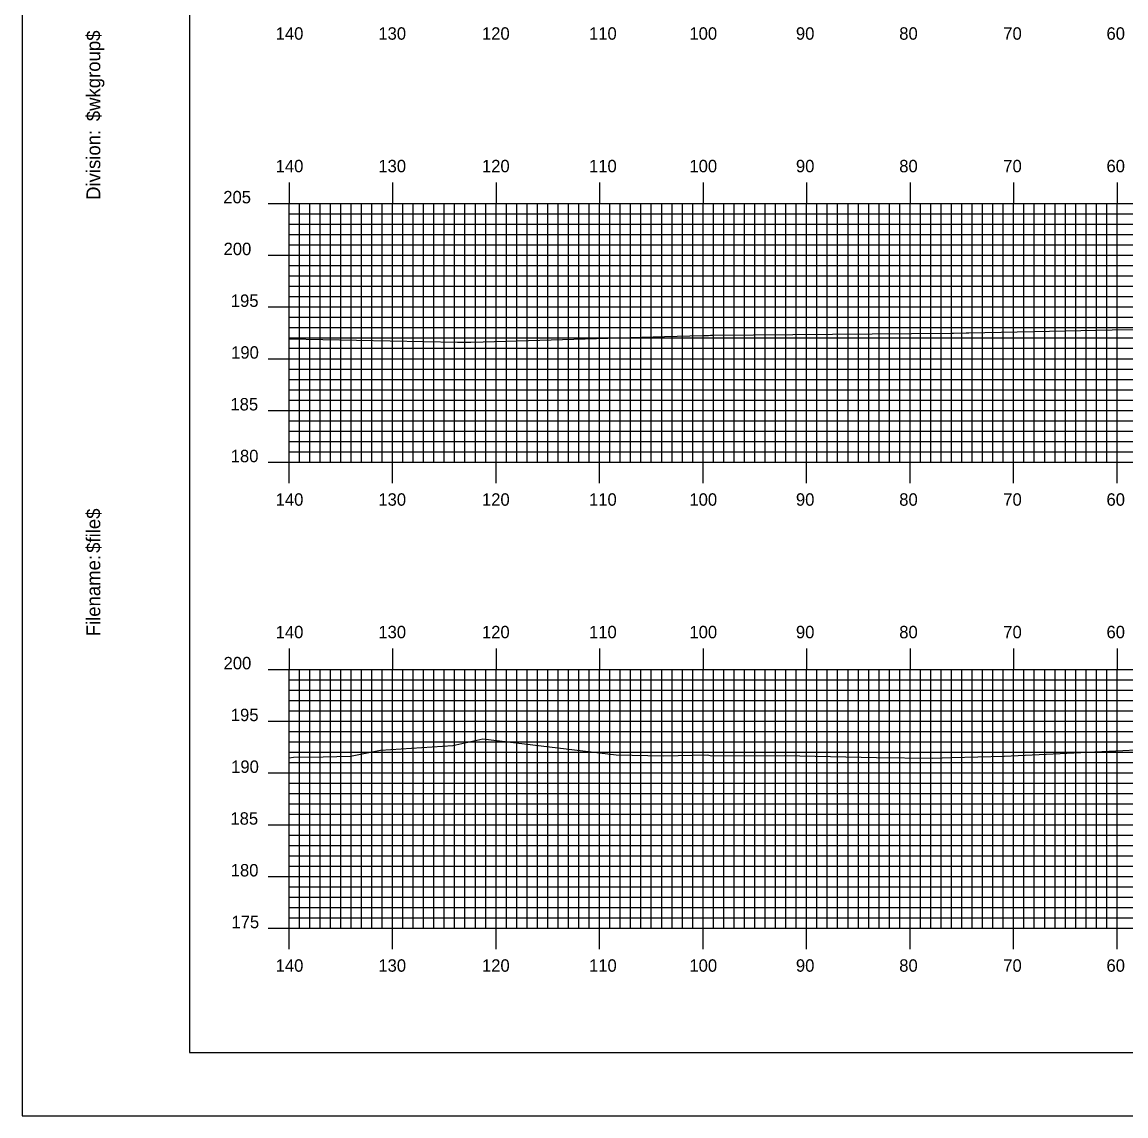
# Model space of a CAD drawing. Extents: x 1798388 to 1798731, y 442591 to 442811.
# Drawn here: x 1798387.7 to 1798494.3, y 442590.5 to 442696.2 of the extents above; entities that cross this region are included whole.
import ezdxf

# ---------------------------------------------------------------- set-up
doc = ezdxf.new("R2010")
doc.units = 0
for name, color, linetype in [('BORDER', 7, 'Continuous'), ('H_V ANNOTATION', 7, 'Continuous'), ('MAJOR', 7, 'Continuous'), ('MINOR', 7, 'Continuous'), ('PLOT BOUNDARY', 7, 'Continuous'), ('S_Roadway_Centerline', 7, 'Continuous')]:
    doc.layers.add(name, color=color, linetype=linetype)

msp = doc.modelspace()

# ---------------------------------------------------------------- linework, layer by layer
at = {"layer": 'BORDER'}
msp.add_lwpolyline([(1798403.87, 442596.67), (1798723.87, 442596.67), (1798723.87, 442806.67), (1798403.87, 442806.67)], close=True, dxfattribs=at)
at = {"layer": 'MAJOR'}
for p, q in [((1798413.47, 442680.67), (1798413.47, 442678.67)), ((1798423.47, 442680.67), (1798423.47, 442678.67)), ((1798433.47, 442680.67), (1798433.47, 442678.67)), ((1798443.47, 442680.67), (1798443.47, 442678.67)), ((1798453.47, 442680.67), (1798453.47, 442678.67)), ((1798463.47, 442680.67), (1798463.47, 442678.67)), ((1798473.47, 442680.67), (1798473.47, 442678.67)), ((1798483.47, 442680.67), (1798483.47, 442678.67)), ((1798493.47, 442680.67), (1798493.47, 442678.67)), ((1798411.47, 442678.67), (1798413.47, 442678.67)), ((1798413.47, 442678.67), (1798693.47, 442678.67)), ((1798413.47, 442653.67), (1798413.47, 442678.67)), ((1798413.47, 442653.67), (1798413.47, 442678.67)), ((1798413.47, 442678.67), (1798693.47, 442678.67)), ((1798423.47, 442653.67), (1798423.47, 442678.67)), ((1798433.47, 442653.67), (1798433.47, 442678.67)), ((1798443.47, 442653.67), (1798443.47, 442678.67)), ((1798453.47, 442653.67), (1798453.47, 442678.67)), ((1798463.47, 442653.67), (1798463.47, 442678.67)), ((1798473.47, 442653.67), (1798473.47, 442678.67)), ((1798483.47, 442653.67), (1798483.47, 442678.67)), ((1798493.47, 442653.67), (1798493.47, 442678.67)), ((1798411.47, 442673.67), (1798413.47, 442673.67)), ((1798413.47, 442673.67), (1798693.47, 442673.67)), ((1798411.47, 442668.67), (1798413.47, 442668.67)), ((1798413.47, 442668.67), (1798693.47, 442668.67)), ((1798411.47, 442663.67), (1798413.47, 442663.67)), ((1798413.47, 442663.67), (1798693.47, 442663.67)), ((1798411.47, 442658.67), (1798413.47, 442658.67)), ((1798413.47, 442658.67), (1798693.47, 442658.67)), ((1798411.47, 442653.67), (1798413.47, 442653.67)), ((1798413.47, 442653.67), (1798693.47, 442653.67)), ((1798413.47, 442653.67), (1798693.47, 442653.67)), ((1798413.47, 442651.66), (1798413.47, 442653.67)), ((1798423.47, 442651.66), (1798423.47, 442653.67)), ((1798433.47, 442651.66), (1798433.47, 442653.67)), ((1798443.47, 442651.66), (1798443.47, 442653.67)), ((1798453.47, 442651.66), (1798453.47, 442653.67)), ((1798463.47, 442651.66), (1798463.47, 442653.67)), ((1798473.47, 442651.66), (1798473.47, 442653.67)), ((1798483.47, 442651.66), (1798483.47, 442653.67)), ((1798493.47, 442651.66), (1798493.47, 442653.67)), ((1798413.47, 442635.67), (1798413.47, 442633.67)), ((1798423.47, 442635.67), (1798423.47, 442633.67)), ((1798433.47, 442635.67), (1798433.47, 442633.67)), ((1798443.47, 442635.67), (1798443.47, 442633.67)), ((1798453.47, 442635.67), (1798453.47, 442633.67)), ((1798463.47, 442635.67), (1798463.47, 442633.67)), ((1798473.47, 442635.67), (1798473.47, 442633.67)), ((1798483.47, 442635.67), (1798483.47, 442633.67)), ((1798493.47, 442635.67), (1798493.47, 442633.67)), ((1798411.47, 442633.67), (1798413.47, 442633.67)), ((1798413.47, 442633.67), (1798693.47, 442633.67)), ((1798413.47, 442608.67), (1798413.47, 442633.67)), ((1798413.47, 442608.67), (1798413.47, 442633.67)), ((1798413.47, 442633.67), (1798693.47, 442633.67)), ((1798423.47, 442608.67), (1798423.47, 442633.67)), ((1798433.47, 442608.67), (1798433.47, 442633.67)), ((1798443.47, 442608.67), (1798443.47, 442633.67)), ((1798453.47, 442608.67), (1798453.47, 442633.67)), ((1798463.47, 442608.67), (1798463.47, 442633.67)), ((1798473.47, 442608.67), (1798473.47, 442633.67)), ((1798483.47, 442608.67), (1798483.47, 442633.67)), ((1798493.47, 442608.67), (1798493.47, 442633.67)), ((1798411.47, 442628.67), (1798413.47, 442628.67)), ((1798413.47, 442628.67), (1798693.47, 442628.67)), ((1798411.47, 442623.67), (1798413.47, 442623.67)), ((1798413.47, 442623.67), (1798693.47, 442623.67)), ((1798411.47, 442618.67), (1798413.47, 442618.67)), ((1798413.47, 442618.67), (1798693.47, 442618.67)), ((1798411.47, 442613.67), (1798413.47, 442613.67)), ((1798413.47, 442613.67), (1798693.47, 442613.67)), ((1798411.47, 442608.67), (1798413.47, 442608.67)), ((1798413.47, 442608.67), (1798693.47, 442608.67)), ((1798413.47, 442608.67), (1798693.47, 442608.67)), ((1798413.47, 442606.66), (1798413.47, 442608.67)), ((1798423.47, 442606.66), (1798423.47, 442608.67)), ((1798433.47, 442606.66), (1798433.47, 442608.67)), ((1798443.47, 442606.66), (1798443.47, 442608.67)), ((1798453.47, 442606.66), (1798453.47, 442608.67)), ((1798463.47, 442606.66), (1798463.47, 442608.67)), ((1798473.47, 442606.66), (1798473.47, 442608.67)), ((1798483.47, 442606.66), (1798483.47, 442608.67)), ((1798493.47, 442606.66), (1798493.47, 442608.67))]:
    msp.add_line(p, q, dxfattribs=at)
at = {"layer": 'MINOR'}
for p, q in [((1798414.47, 442653.67), (1798414.47, 442678.67)), ((1798415.47, 442653.67), (1798415.47, 442678.67)), ((1798416.47, 442653.67), (1798416.47, 442678.67)), ((1798417.47, 442653.67), (1798417.47, 442678.67)), ((1798418.47, 442653.67), (1798418.47, 442678.67)), ((1798419.47, 442653.67), (1798419.47, 442678.67)), ((1798420.47, 442653.67), (1798420.47, 442678.67)), ((1798421.47, 442653.67), (1798421.47, 442678.67)), ((1798422.47, 442653.67), (1798422.47, 442678.67)), ((1798424.47, 442653.67), (1798424.47, 442678.67)), ((1798425.47, 442653.67), (1798425.47, 442678.67)), ((1798426.47, 442653.67), (1798426.47, 442678.67)), ((1798427.47, 442653.67), (1798427.47, 442678.67)), ((1798428.47, 442653.67), (1798428.47, 442678.67)), ((1798429.47, 442653.67), (1798429.47, 442678.67)), ((1798430.47, 442653.67), (1798430.47, 442678.67)), ((1798431.47, 442653.67), (1798431.47, 442678.67)), ((1798432.47, 442653.67), (1798432.47, 442678.67)), ((1798434.47, 442653.67), (1798434.47, 442678.67)), ((1798435.47, 442653.67), (1798435.47, 442678.67)), ((1798436.47, 442653.67), (1798436.47, 442678.67)), ((1798437.47, 442653.67), (1798437.47, 442678.67)), ((1798438.47, 442653.67), (1798438.47, 442678.67)), ((1798439.47, 442653.67), (1798439.47, 442678.67)), ((1798440.47, 442653.67), (1798440.47, 442678.67)), ((1798441.47, 442653.67), (1798441.47, 442678.67)), ((1798442.47, 442653.67), (1798442.47, 442678.67)), ((1798444.47, 442653.67), (1798444.47, 442678.67)), ((1798445.47, 442653.67), (1798445.47, 442678.67)), ((1798446.47, 442653.67), (1798446.47, 442678.67)), ((1798447.47, 442653.67), (1798447.47, 442678.67)), ((1798448.47, 442653.67), (1798448.47, 442678.67)), ((1798449.47, 442653.67), (1798449.47, 442678.67)), ((1798450.47, 442653.67), (1798450.47, 442678.67)), ((1798451.47, 442653.67), (1798451.47, 442678.67)), ((1798452.47, 442653.67), (1798452.47, 442678.67)), ((1798454.47, 442653.67), (1798454.47, 442678.67)), ((1798455.47, 442653.67), (1798455.47, 442678.67)), ((1798456.47, 442653.67), (1798456.47, 442678.67)), ((1798457.47, 442653.67), (1798457.47, 442678.67)), ((1798458.47, 442653.67), (1798458.47, 442678.67)), ((1798459.47, 442653.67), (1798459.47, 442678.67)), ((1798460.47, 442653.67), (1798460.47, 442678.67)), ((1798461.47, 442653.67), (1798461.47, 442678.67)), ((1798462.47, 442653.67), (1798462.47, 442678.67)), ((1798464.47, 442653.67), (1798464.47, 442678.67)), ((1798465.47, 442653.67), (1798465.47, 442678.67)), ((1798466.47, 442653.67), (1798466.47, 442678.67)), ((1798467.47, 442653.67), (1798467.47, 442678.67)), ((1798468.47, 442653.67), (1798468.47, 442678.67)), ((1798469.47, 442653.67), (1798469.47, 442678.67)), ((1798470.47, 442653.67), (1798470.47, 442678.67)), ((1798471.47, 442653.67), (1798471.47, 442678.67)), ((1798472.47, 442653.67), (1798472.47, 442678.67)), ((1798474.47, 442653.67), (1798474.47, 442678.67)), ((1798475.47, 442653.67), (1798475.47, 442678.67)), ((1798476.47, 442653.67), (1798476.47, 442678.67)), ((1798477.47, 442653.67), (1798477.47, 442678.67)), ((1798478.47, 442653.67), (1798478.47, 442678.67)), ((1798479.47, 442653.67), (1798479.47, 442678.67)), ((1798480.47, 442653.67), (1798480.47, 442678.67)), ((1798481.47, 442653.67), (1798481.47, 442678.67)), ((1798482.47, 442653.67), (1798482.47, 442678.67)), ((1798484.47, 442653.67), (1798484.47, 442678.67)), ((1798485.47, 442653.67), (1798485.47, 442678.67)), ((1798486.47, 442653.67), (1798486.47, 442678.67)), ((1798487.47, 442653.67), (1798487.47, 442678.67)), ((1798488.47, 442653.67), (1798488.47, 442678.67)), ((1798489.47, 442653.67), (1798489.47, 442678.67)), ((1798490.47, 442653.67), (1798490.47, 442678.67)), ((1798491.47, 442653.67), (1798491.47, 442678.67)), ((1798492.47, 442653.67), (1798492.47, 442678.67)), ((1798413.47, 442677.67), (1798693.47, 442677.67)), ((1798413.47, 442677.67), (1798415.47, 442677.67)), ((1798413.47, 442676.67), (1798693.47, 442676.67)), ((1798413.47, 442676.67), (1798415.47, 442676.67)), ((1798413.47, 442675.67), (1798693.47, 442675.67)), ((1798413.47, 442675.67), (1798415.47, 442675.67)), ((1798413.47, 442674.67), (1798693.47, 442674.67)), ((1798413.47, 442674.67), (1798415.47, 442674.67)), ((1798413.47, 442672.67), (1798693.47, 442672.67)), ((1798413.47, 442672.67), (1798415.47, 442672.67)), ((1798413.47, 442671.67), (1798693.47, 442671.67)), ((1798413.47, 442671.67), (1798415.47, 442671.67)), ((1798413.47, 442670.67), (1798693.47, 442670.67)), ((1798413.47, 442670.67), (1798415.47, 442670.67)), ((1798413.47, 442669.67), (1798693.47, 442669.67)), ((1798413.47, 442669.67), (1798415.47, 442669.67)), ((1798413.47, 442667.67), (1798693.47, 442667.67)), ((1798413.47, 442667.67), (1798415.47, 442667.67)), ((1798413.47, 442666.67), (1798693.47, 442666.67)), ((1798413.47, 442666.67), (1798415.47, 442666.67)), ((1798413.47, 442665.67), (1798693.47, 442665.67)), ((1798413.47, 442665.67), (1798415.47, 442665.67)), ((1798413.47, 442664.67), (1798693.47, 442664.67)), ((1798413.47, 442664.67), (1798415.47, 442664.67)), ((1798413.47, 442662.67), (1798693.47, 442662.67)), ((1798413.47, 442662.67), (1798415.47, 442662.67)), ((1798413.47, 442661.67), (1798693.47, 442661.67)), ((1798413.47, 442661.67), (1798415.47, 442661.67)), ((1798413.47, 442660.67), (1798693.47, 442660.67)), ((1798413.47, 442660.67), (1798415.47, 442660.67)), ((1798413.47, 442659.67), (1798693.47, 442659.67)), ((1798413.47, 442659.67), (1798415.47, 442659.67)), ((1798413.47, 442657.67), (1798693.47, 442657.67)), ((1798413.47, 442657.67), (1798415.47, 442657.67)), ((1798413.47, 442656.67), (1798693.47, 442656.67)), ((1798413.47, 442656.67), (1798415.47, 442656.67)), ((1798413.47, 442655.67), (1798693.47, 442655.67)), ((1798413.47, 442655.67), (1798415.47, 442655.67)), ((1798413.47, 442654.67), (1798693.47, 442654.67)), ((1798413.47, 442654.67), (1798415.47, 442654.67)), ((1798414.47, 442608.67), (1798414.47, 442633.67)), ((1798415.47, 442608.67), (1798415.47, 442633.67)), ((1798416.47, 442608.67), (1798416.47, 442633.67)), ((1798417.47, 442608.67), (1798417.47, 442633.67)), ((1798418.47, 442608.67), (1798418.47, 442633.67)), ((1798419.47, 442608.67), (1798419.47, 442633.67)), ((1798420.47, 442608.67), (1798420.47, 442633.67)), ((1798421.47, 442608.67), (1798421.47, 442633.67)), ((1798422.47, 442608.67), (1798422.47, 442633.67)), ((1798424.47, 442608.67), (1798424.47, 442633.67)), ((1798425.47, 442608.67), (1798425.47, 442633.67)), ((1798426.47, 442608.67), (1798426.47, 442633.67)), ((1798427.47, 442608.67), (1798427.47, 442633.67)), ((1798428.47, 442608.67), (1798428.47, 442633.67)), ((1798429.47, 442608.67), (1798429.47, 442633.67)), ((1798430.47, 442608.67), (1798430.47, 442633.67)), ((1798431.47, 442608.67), (1798431.47, 442633.67)), ((1798432.47, 442608.67), (1798432.47, 442633.67)), ((1798434.47, 442608.67), (1798434.47, 442633.67)), ((1798435.47, 442608.67), (1798435.47, 442633.67)), ((1798436.47, 442608.67), (1798436.47, 442633.67)), ((1798437.47, 442608.67), (1798437.47, 442633.67)), ((1798438.47, 442608.67), (1798438.47, 442633.67)), ((1798439.47, 442608.67), (1798439.47, 442633.67)), ((1798440.47, 442608.67), (1798440.47, 442633.67)), ((1798441.47, 442608.67), (1798441.47, 442633.67)), ((1798442.47, 442608.67), (1798442.47, 442633.67)), ((1798444.47, 442608.67), (1798444.47, 442633.67)), ((1798445.47, 442608.67), (1798445.47, 442633.67)), ((1798446.47, 442608.67), (1798446.47, 442633.67)), ((1798447.47, 442608.67), (1798447.47, 442633.67)), ((1798448.47, 442608.67), (1798448.47, 442633.67)), ((1798449.47, 442608.67), (1798449.47, 442633.67)), ((1798450.47, 442608.67), (1798450.47, 442633.67)), ((1798451.47, 442608.67), (1798451.47, 442633.67)), ((1798452.47, 442608.67), (1798452.47, 442633.67)), ((1798454.47, 442608.67), (1798454.47, 442633.67)), ((1798455.47, 442608.67), (1798455.47, 442633.67)), ((1798456.47, 442608.67), (1798456.47, 442633.67)), ((1798457.47, 442608.67), (1798457.47, 442633.67)), ((1798458.47, 442608.67), (1798458.47, 442633.67)), ((1798459.47, 442608.67), (1798459.47, 442633.67)), ((1798460.47, 442608.67), (1798460.47, 442633.67)), ((1798461.47, 442608.67), (1798461.47, 442633.67)), ((1798462.47, 442608.67), (1798462.47, 442633.67)), ((1798464.47, 442608.67), (1798464.47, 442633.67)), ((1798465.47, 442608.67), (1798465.47, 442633.67)), ((1798466.47, 442608.67), (1798466.47, 442633.67)), ((1798467.47, 442608.67), (1798467.47, 442633.67)), ((1798468.47, 442608.67), (1798468.47, 442633.67)), ((1798469.47, 442608.67), (1798469.47, 442633.67)), ((1798470.47, 442608.67), (1798470.47, 442633.67)), ((1798471.47, 442608.67), (1798471.47, 442633.67)), ((1798472.47, 442608.67), (1798472.47, 442633.67)), ((1798474.47, 442608.67), (1798474.47, 442633.67)), ((1798475.47, 442608.67), (1798475.47, 442633.67)), ((1798476.47, 442608.67), (1798476.47, 442633.67)), ((1798477.47, 442608.67), (1798477.47, 442633.67)), ((1798478.47, 442608.67), (1798478.47, 442633.67)), ((1798479.47, 442608.67), (1798479.47, 442633.67)), ((1798480.47, 442608.67), (1798480.47, 442633.67)), ((1798481.47, 442608.67), (1798481.47, 442633.67)), ((1798482.47, 442608.67), (1798482.47, 442633.67)), ((1798484.47, 442608.67), (1798484.47, 442633.67)), ((1798485.47, 442608.67), (1798485.47, 442633.67)), ((1798486.47, 442608.67), (1798486.47, 442633.67)), ((1798487.47, 442608.67), (1798487.47, 442633.67)), ((1798488.47, 442608.67), (1798488.47, 442633.67)), ((1798489.47, 442608.67), (1798489.47, 442633.67)), ((1798490.47, 442608.67), (1798490.47, 442633.67)), ((1798491.47, 442608.67), (1798491.47, 442633.67)), ((1798492.47, 442608.67), (1798492.47, 442633.67)), ((1798413.47, 442632.67), (1798693.47, 442632.67)), ((1798413.47, 442632.67), (1798415.47, 442632.67)), ((1798413.47, 442631.67), (1798693.47, 442631.67)), ((1798413.47, 442631.67), (1798415.47, 442631.67)), ((1798413.47, 442630.67), (1798693.47, 442630.67)), ((1798413.47, 442630.67), (1798415.47, 442630.67)), ((1798413.47, 442629.67), (1798693.47, 442629.67)), ((1798413.47, 442629.67), (1798415.47, 442629.67)), ((1798413.47, 442627.67), (1798693.47, 442627.67)), ((1798413.47, 442627.67), (1798415.47, 442627.67)), ((1798413.47, 442626.67), (1798693.47, 442626.67)), ((1798413.47, 442626.67), (1798415.47, 442626.67)), ((1798413.47, 442625.67), (1798693.47, 442625.67)), ((1798413.47, 442625.67), (1798415.47, 442625.67)), ((1798413.47, 442624.67), (1798693.47, 442624.67)), ((1798413.47, 442624.67), (1798415.47, 442624.67)), ((1798413.47, 442622.67), (1798693.47, 442622.67)), ((1798413.47, 442622.67), (1798415.47, 442622.67)), ((1798413.47, 442621.67), (1798693.47, 442621.67)), ((1798413.47, 442621.67), (1798415.47, 442621.67)), ((1798413.47, 442620.67), (1798693.47, 442620.67)), ((1798413.47, 442620.67), (1798415.47, 442620.67)), ((1798413.47, 442619.67), (1798693.47, 442619.67)), ((1798413.47, 442619.67), (1798415.47, 442619.67)), ((1798413.47, 442617.67), (1798693.47, 442617.67)), ((1798413.47, 442617.67), (1798415.47, 442617.67)), ((1798413.47, 442616.67), (1798693.47, 442616.67)), ((1798413.47, 442616.67), (1798415.47, 442616.67)), ((1798413.47, 442615.67), (1798693.47, 442615.67)), ((1798413.47, 442615.67), (1798415.47, 442615.67)), ((1798413.47, 442614.67), (1798693.47, 442614.67)), ((1798413.47, 442614.67), (1798415.47, 442614.67)), ((1798413.47, 442612.67), (1798693.47, 442612.67)), ((1798413.47, 442612.67), (1798415.47, 442612.67)), ((1798413.47, 442611.67), (1798693.47, 442611.67)), ((1798413.47, 442611.67), (1798415.47, 442611.67)), ((1798413.47, 442610.67), (1798693.47, 442610.67)), ((1798413.47, 442610.67), (1798415.47, 442610.67)), ((1798413.47, 442609.67), (1798693.47, 442609.67)), ((1798413.47, 442609.67), (1798415.47, 442609.67))]:
    msp.add_line(p, q, dxfattribs=at)
at = {"layer": 'PLOT BOUNDARY'}
msp.add_lwpolyline([(1798387.68, 442590.55), (1798727.68, 442590.55), (1798727.68, 442810.55), (1798387.68, 442810.55)], close=True, dxfattribs=at)
at = {"layer": 'S_Roadway_Centerline'}
for points in [[(1798413.47, 442665.57), (1798429.76, 442665.26), (1798431.05, 442665.27), (1798432.23, 442665.29), (1798449.74, 442665.81), (1798453.4, 442665.92), (1798453.62, 442665.92), (1798453.82, 442665.92), (1798453.89, 442665.92), (1798453.99, 442665.92), (1798454.19, 442665.93), (1798454.5, 442665.93), (1798477.45, 442666.13), (1798477.67, 442666.13), (1798478.9, 442666.15), (1798479.15, 442666.16), (1798486.95, 442666.32), (1798492.98, 442666.44), (1798497.86, 442666.51)], [(1798413.47, 442625.14), (1798413.91, 442625.2), (1798416.78, 442625.22), (1798419.4, 442625.28), (1798422.3, 442625.86), (1798429.3, 442626.32), (1798432.2, 442626.96), (1798445.09, 442625.41), (1798449.68, 442625.32), (1798453.88, 442625.42), (1798454.32, 442625.32), (1798461.34, 442625.35), (1798470.21, 442625.17), (1798475.66, 442625.09), (1798477.46, 442625.16), (1798482.57, 442625.27), (1798494.03, 442625.84), (1798495.29, 442625.9)]]:
    msp.add_lwpolyline(points, dxfattribs=at)

# ---------------------------------------------------------------- texts
at = {"layer": 'BORDER'}
for s, p in [('$wkgroup$', (1798395.24, 442686.6)), ('Division:', (1798395.24, 442679)), ('$file$', (1798395.24, 442644.92)), ('Filename:', (1798395.24, 442636.86))]:
    msp.add_text(s, height=1.339, rotation=90, dxfattribs=at).set_placement(p)
at = {"layer": 'H_V ANNOTATION'}
for s, p in [('140', (1798412.18, 442694.47)), ('130', (1798422.1, 442694.47)), ('120', (1798432.11, 442694.47)), ('110', (1798442.45, 442694.47)), ('100', (1798452.15, 442694.47)), ('90', (1798462.44, 442694.47)), ('80', (1798472.42, 442694.47)), ('70', (1798482.47, 442694.47)), ('60', (1798492.44, 442694.47)), ('140', (1798412.18, 442681.67)), ('130', (1798422.1, 442681.67)), ('120', (1798432.11, 442681.67)), ('110', (1798442.45, 442681.67)), ('100', (1798452.15, 442681.67)), ('90', (1798462.44, 442681.67)), ('80', (1798472.42, 442681.67)), ('70', (1798482.47, 442681.67)), ('60', (1798492.44, 442681.67)), ('205', (1798407.12, 442678.67)), ('200', (1798407.15, 442673.67)), ('195', (1798407.85, 442668.67)), ('190', (1798407.88, 442663.67)), ('185', (1798407.81, 442658.67)), ('180', (1798407.84, 442653.67)), ('140', (1798412.18, 442649.47)), ('130', (1798422.1, 442649.47)), ('120', (1798432.11, 442649.47)), ('110', (1798442.45, 442649.47)), ('100', (1798452.15, 442649.47)), ('90', (1798462.44, 442649.47)), ('80', (1798472.42, 442649.47)), ('70', (1798482.47, 442649.47)), ('60', (1798492.44, 442649.47)), ('140', (1798412.18, 442636.67)), ('130', (1798422.1, 442636.67)), ('120', (1798432.11, 442636.67)), ('110', (1798442.45, 442636.67)), ('100', (1798452.15, 442636.67)), ('90', (1798462.44, 442636.67)), ('80', (1798472.42, 442636.67)), ('70', (1798482.47, 442636.67)), ('60', (1798492.44, 442636.67)), ('200', (1798407.15, 442633.67)), ('195', (1798407.85, 442628.67)), ('190', (1798407.88, 442623.67)), ('185', (1798407.81, 442618.67)), ('180', (1798407.84, 442613.67)), ('175', (1798407.91, 442608.67)), ('140', (1798412.18, 442604.47)), ('130', (1798422.1, 442604.47)), ('120', (1798432.11, 442604.47)), ('110', (1798442.45, 442604.47)), ('100', (1798452.15, 442604.47)), ('90', (1798462.44, 442604.47)), ('80', (1798472.42, 442604.47)), ('70', (1798482.47, 442604.47)), ('60', (1798492.44, 442604.47))]:
    msp.add_text(s, height=1.2, dxfattribs=at).set_placement(p)
at = {"layer": 'MAJOR'}
for p in [(1798413.46, 442653.67), (1798413.46, 442608.67)]:
    msp.add_text('-', height=0.012, dxfattribs=at).set_placement(p)

doc.saveas('drawing.dxf')
